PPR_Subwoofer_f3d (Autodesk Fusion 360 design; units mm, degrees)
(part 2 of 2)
sketch "Assembly Clamp" plane through (3.4, 0, 0) normal (1, 0, 0) x axis (0, 1, 0)
  line L1 (23.8, 56.5) -> (23.8, 123.5)
  line L2 (58, 23.3) -> (57, 23.3)
  line L3 (91.2, 123.5) -> (91.2, 56.5)
  line L4 (57, 156.7) -> (58, 156.7)
  line L5 (58, 155.5) -> (57, 155.5)
  line L6 (90, 56.5) -> (90, 123.5)
  line L7 (57, 24.5) -> (58, 24.5)
  line L8 (25, 123.5) -> (25, 56.5)
  line L9 (9, 56.5) -> (9, 123.5)
  line L10 (58, 8.5) -> (57, 8.5)
  line L11 (106, 123.5) -> (106, 56.5)
  line L12 (57, 171.5) -> (58, 171.5)
  line L13 (58, 167.5) -> (57, 167.5)
  line L14 (102, 56.5) -> (102, 123.5)
  line L15 (57, 12.5) -> (58, 12.5)
  line L16 (13, 123.5) -> (13, 56.5)
  line L17 (85.9, 123.5) -> (86.4, 123.5)
  line L18 (85.9, 122.5) -> (85.9, 123.5)
  line L19 (86.4, 122.5) -> (85.9, 122.5)
  line L20 (86.4, 123.5) -> (86.4, 122.5)
  line L21 (85.7, 56.5) -> (85.7, 123.5)
  line L22 (58, 151.2) -> (57, 151.2)
  line L23 (10, 56.5) -> (10, 123.5)
  line L24 (58, 9.5) -> (57, 9.5)
  line L25 (105, 123.5) -> (105, 56.5)
  line L26 (57, 170.5) -> (58, 170.5)
  line L27 (58, 157.1) -> (57, 157.1)
  line L28 (91.6, 56.5) -> (91.6, 123.5)
  line L29 (57, 22.9) -> (58, 22.9)
  line L30 (23.4, 123.5) -> (23.4, 56.5)
  line L31 (86.4, 123.5) -> (86.4, 56.5)
  line L32 (57, 151.9) -> (58, 151.9)
  line L33 (28.6, 56.5) -> (28.6, 123.5)
  line L34 (58, 28.1) -> (57, 28.1)
  line L35 (14.6, 56.5) -> (14.6, 123.5)
  line L36 (58, 14.1) -> (57, 14.1)
  line L37 (100.4, 123.5) -> (100.4, 56.5)
  line L38 (57, 165.9) -> (58, 165.9)
  line L39 (9.4, 123.5) -> (9.4, 56.5)
  line L40 (58, 171.1) -> (57, 171.1)
  line L41 (105.6, 56.5) -> (105.6, 123.5)
  line L42 (57, 8.9) -> (58, 8.9)
  line L43 (28.6, 90) -> (85.7, 90)
  line L44 (57.5, 111.9) -> (57.5, 151.9)
  line L45 (29.1, 123.5) -> (28.6, 123.5)
  line L46 (29.1, 122.5) -> (29.1, 123.5)
  line L47 (28.6, 122.5) -> (29.1, 122.5)
  line L48 (29.1, 56.5) -> (28.6, 56.5)
  line L49 (29.1, 57.5) -> (29.1, 56.5)
  line L50 (28.6, 57.5) -> (29.1, 57.5)
  line L51 (85.9, 56.5) -> (86.4, 56.5)
  line L52 (85.9, 57.5) -> (85.9, 56.5)
  line L53 (86.4, 57.5) -> (85.9, 57.5)
  line L54 (57, 151.9) -> (58, 151.9)
  line L55 (57, 151.35) -> (57, 151.9)
  line L56 (58, 151.35) -> (57, 151.35)
  line L57 (58, 151.9) -> (58, 151.35)
  line L58 (58, 28.1) -> (58, 28.65)
  line L59 (58, 28.65) -> (57, 28.65)
  line L60 (57, 28.65) -> (57, 28.1)
  arc A1 centre (57, 123.5) radius 33.2 clockwise from (23.8, 123.5) to (57, 156.7)
  arc A2 centre (57, 56.5) radius 33.2 clockwise from (57, 23.3) to (23.8, 56.5)
  arc A3 centre (58, 56.5) radius 33.2 clockwise from (91.2, 56.5) to (58, 23.3)
  arc A4 centre (58, 123.5) radius 33.2 clockwise from (58, 156.7) to (91.2, 123.5)
  arc A5 centre (58, 123.5) radius 32 clockwise from (58, 155.5) to (90, 123.5)
  arc A6 centre (58, 56.5) radius 32 clockwise from (90, 56.5) to (58, 24.5)
  arc A7 centre (57, 56.5) radius 32 clockwise from (57, 24.5) to (25, 56.5)
  arc A8 centre (57, 123.5) radius 32 clockwise from (25, 123.5) to (57, 155.5)
  arc A9 centre (57, 123.5) radius 48 clockwise from (9, 123.5) to (57, 171.5)
  arc A10 centre (57, 56.5) radius 48 clockwise from (57, 8.5) to (9, 56.5)
  arc A11 centre (58, 56.5) radius 48 clockwise from (106, 56.5) to (58, 8.5)
  arc A12 centre (58, 123.5) radius 48 clockwise from (58, 171.5) to (106, 123.5)
  arc A13 centre (58, 123.5) radius 44 clockwise from (58, 167.5) to (102, 123.5)
  arc A14 centre (58, 56.5) radius 44 clockwise from (102, 56.5) to (58, 12.5)
  arc A15 centre (57, 56.5) radius 44 clockwise from (57, 12.5) to (13, 56.5)
  arc A16 centre (57, 123.5) radius 44 clockwise from (13, 123.5) to (57, 167.5)
  arc A17 centre (57, 123.5) radius 47 clockwise from (10, 123.5) to (57, 170.5)
  arc A18 centre (57, 56.5) radius 47 clockwise from (57, 9.5) to (10, 56.5)
  arc A19 centre (58, 56.5) radius 47 clockwise from (105, 56.5) to (58, 9.5)
  arc A20 centre (58, 123.5) radius 47 clockwise from (58, 170.5) to (105, 123.5)
  arc A21 centre (58, 123.5) radius 33.6 clockwise from (58, 157.1) to (91.6, 123.5)
  arc A22 centre (58, 56.5) radius 33.6 clockwise from (91.6, 56.5) to (58, 22.9)
  arc A23 centre (57, 56.5) radius 33.6 clockwise from (57, 22.9) to (23.4, 56.5)
  arc A24 centre (57, 123.5) radius 33.6 clockwise from (23.4, 123.5) to (57, 157.1)
  arc A25 centre (58, 56.5) radius 28.4 clockwise from (86.4, 56.5) to (58, 28.1)
  arc A26 centre (58, 123.5) radius 28.4 clockwise from (58, 151.9) to (86.4, 123.5)
  arc A27 centre (57, 123.5) radius 28.4 clockwise from (28.6, 123.5) to (57, 151.9)
  arc A28 centre (57, 56.5) radius 28.4 clockwise from (57, 28.1) to (28.6, 56.5)
  arc A29 centre (57, 123.5) radius 42.4 clockwise from (14.6, 123.5) to (57, 165.9)
  arc A30 centre (57, 56.5) radius 42.4 clockwise from (57, 14.1) to (14.6, 56.5)
  arc A31 centre (58, 56.5) radius 42.4 clockwise from (100.4, 56.5) to (58, 14.1)
  arc A32 centre (58, 123.5) radius 42.4 clockwise from (58, 165.9) to (100.4, 123.5)
  arc A33 centre (57, 123.5) radius 47.6 clockwise from (9.4, 123.5) to (57, 171.1)
  arc A34 centre (58, 123.5) radius 47.6 clockwise from (58, 171.1) to (105.6, 123.5)
  arc A35 centre (58, 56.5) radius 47.6 clockwise from (105.6, 56.5) to (58, 8.9)
  arc A36 centre (57, 56.5) radius 47.6 clockwise from (57, 8.9) to (9.4, 56.5)
  point P44 (86.4, 122.5)
  point P75 (86.4, 123.5)
  point P101 (86.4, 123.5)
  point P102 (85.7, 90)
  point P103 (28.6, 90)
  point P104 (57.5, 151.9)
  point P42 (85.9, 123.5)
  point P107 (29.1, 123.5)
  point P43 (85.9, 122.5)
  point P108 (29.1, 122.5)
  point P109 (28.6, 122.5)
  point P106 (28.6, 123.5)
  point P115 (85.9, 56.5)
  point P116 (85.9, 57.5)
  point P117 (86.4, 57.5)
  point P114 (86.4, 56.5)
  point P110 (28.6, 56.5)
  point P111 (29.1, 56.5)
  point P112 (29.1, 57.5)
  point P113 (28.6, 57.5)
  point P76 (58, 151.9)
  point P118 (58, 151.9)
  point P77 (57, 151.9)
  point P121 (57, 151.9)
  point P123 (58, 28.1)
  point P119 (57, 151.35)
  point P124 (57, 28.65)
  point P120 (58, 151.35)
  point P122 (58, 28.65)
  point P125 (57, 28.1)
  point P105 (57.5, 111.9)
  horizontal L17
  vertical L18
  horizontal L19
  vertical L20
  coincident P44 L31
  coincident P75 P101
  midpoint L21 P102
  midpoint L33 P103
  vertical L44
  midpoint L32 P104
  symmetric P42 L44 P107
  symmetric P43 L44 P108
  symmetric P44 L44 P109
  symmetric P101 L44 P106
  symmetric P42 L43 P115
  symmetric P43 L43 P116
  symmetric P44 L43 P117
  symmetric P101 L43 P114
  symmetric L43 P106 P110
  symmetric L43 P107 P111
  symmetric L43 P108 P112
  symmetric L43 P109 P113
  horizontal L54
  vertical L55
  horizontal L56
  vertical L57
  coincident P76 P118
  coincident P77 P121
  symmetric L43 P118 P123
  symmetric L43 P119 P124
  symmetric L43 P120 P122
  symmetric L43 P121 P125
  dimension "d202" distance P44 P75 = 1
  dimension "d203" distance L18 L21 = 0.2
  dimension "d206" = -1
  dimension "d210" distance P104 P105 = 40
  dimension "d211" distance L22 L56 = 0.15
extrude "Extrude1" new body sketch "Assembly Clamp" profile of A1 L1 A2 L2 A3 L3 A4 L4 L5 A5 L6 A6 L7 A7 L8 A8 L13 A13 L14 A14 L15 A15 L16 A16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 along normal blind 7 bodies "Assembly clamp for glueing"
align "Align1"
move "Move2" TranslateX -130 TranslateY 80 TranslateZ 0
align "Align1"
align "Align1"
align "Align2"
align "Align3"
align "Align7"
align "Align2"
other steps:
base_feature "Base Feature1" bodies "Enclosure", "Enclosure - terminal posts"
base_feature "Base Feature1" bodies "Front Baffle", "Front Baffle Textured"
base_feature "Base Feature1" bodies "Suspension Trimmed Flange"
base_feature "Base Feature1" bodies "Enclosure", "Enclosure - Peerless P830878"
base_feature "Base Feature2" bodies "Enclosure (1)", "Enclosure - Peerless 830878 - Terminal Posts"
base_feature "Base Feature2" bodies "Ring Piece", "Ring Piece (1)"
create_component "CreateComponent1"
create_component "CreateComponent2"
create_component "CreateComponent1"
create_component "CreateComponent2"
create_component "CreateComponent3"
create_component "CreateComponent4"
remove_body "RemoveBody2"
create_component "CreateComponent4"
named bodies: "Enclosure", "Internal volume", "Front Baffle", "Suspension", "Ring Piece", "Center Piece", "Cut-out", "Suspension Trimmed Flange", "Center piece 2", "Ring Piece (1)", "lug", "brace", "lug (1)", "brace (1)", "Front Baffle Textured", "Assembly clamp for glueing", "Enclosure - Peerless P830878", "Enclosure - terminal posts", "Enclosure (1)", "Enclosure - Peerless 830878 - Terminal Posts"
